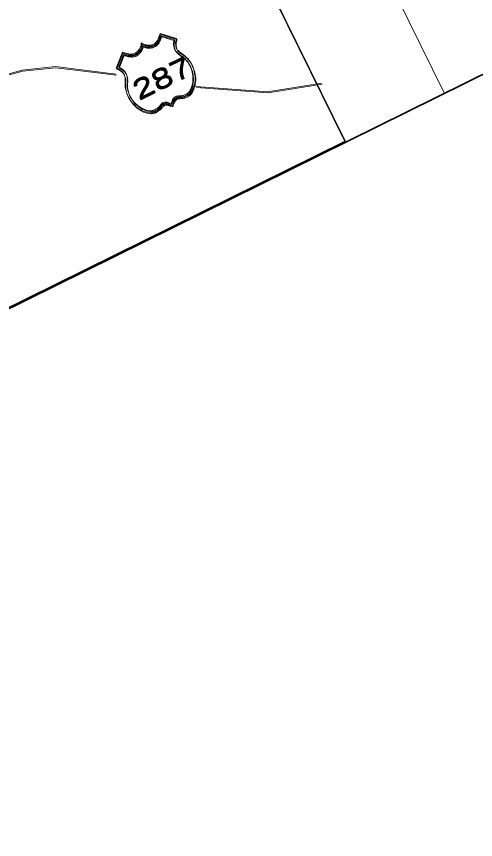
# Model space of a CAD drawing. Extents: x 2356606 to 2371222, y 6973096 to 6982644.
# Drawn here: x 2357523 to 2357641.7, y 6973406.8 to 6973619.6 of the extents above; entities that cross this region are included whole.
import ezdxf

# ---------------------------------------------------------------- set-up
doc = ezdxf.new("R2010")
doc.units = 0
doc.header["$LTSCALE"] = 2
doc.layers.add('62', color=7, linetype='Continuous', lineweight=13)
doc.layers.add('63', color=7, linetype='Continuous', lineweight=13)

msp = doc.modelspace()

# ---------------------------------------------------------------- linework, layer by layer
at = {"layer": '62'}
for p, q in [((2357278.212, 6974319.925), (2357633.685, 6973599.663)), ((2357533.197, 6973606.326), (2357548.847, 6973604.414)), ((2357602.042, 6973602.084), (2357588.059, 6973599.854)), ((2357588.059, 6973599.854), (2357569.519, 6973601.167))]:
    msp.add_line(p, q, dxfattribs=at)
at = {"layer": '62', "lineweight": 25}
msp.add_lwpolyline([(2356999.05, 6973805.301), (2357204.965, 6973388.075), (2357608.13, 6973587.05), (2357402.214, 6974004.278)], dxfattribs=at)
at = {"layer": '62'}
for points in [[(2357533.197, 6973606.326), (2357524.62, 6973605.458), (2357515.167, 6973602.848), (2357498.075, 6973598.379), (2357486.108, 6973599.448), (2357477.959, 6973600.342), (2357467.348, 6973601.705), (2357455.307, 6973606.229), (2357445.287, 6973612.652), (2357434.9, 6973620.272), (2357421.318, 6973628.676), (2357410.865, 6973633.077), (2357401.996, 6973638.183), (2357391.636, 6973644.988), (2357385.904, 6973647.606), (2357373.931, 6973655.899)], [(2357548.927, 6973605.934), (2357550.526, 6973610.06), (2357550.769, 6973609.979), (2357551.018, 6973609.876), (2357551.269, 6973609.825), (2357551.491, 6973609.732), (2357551.744, 6973609.684), (2357551.965, 6973609.64), (2357552.185, 6973609.6), (2357552.426, 6973609.567), (2357552.608, 6973609.556), (2357552.829, 6973609.565), (2357553.03, 6973609.563), (2357553.233, 6973609.613), (2357553.415, 6973609.653), (2357553.573, 6973609.684), (2357553.777, 6973609.781), (2357553.958, 6973609.871), (2357554.06, 6973609.972), (2357554.179, 6973610.082), (2357554.331, 6973610.182), (2357554.462, 6973610.322), (2357554.596, 6973610.463), (2357554.696, 6973610.613), (2357554.829, 6973610.753), (2357554.95, 6973610.912), (2357555.032, 6973611.103), (2357555.133, 6973611.304), (2357555.215, 6973611.495), (2357555.305, 6973611.664), (2357555.337, 6973611.858), (2357555.388, 6973612.057), (2357555.36, 6973612.269), (2357555.39, 6973612.46), (2357555.56, 6973612.37), (2357555.752, 6973612.238), (2357555.951, 6973612.136), (2357556.134, 6973612.073), (2357556.345, 6973612.002), (2357556.565, 6973611.96), (2357556.755, 6973611.93), (2357556.967, 6973611.908), (2357557.176, 6973611.887), (2357557.369, 6973611.857), (2357557.591, 6973611.914), (2357557.774, 6973611.905), (2357558.015, 6973611.973), (2357558.176, 6973612.004), (2357558.397, 6973612.061), (2357558.57, 6973612.122), (2357558.709, 6973612.192), (2357558.88, 6973612.302), (2357558.973, 6973612.422), (2357559.133, 6973612.55), (2357559.265, 6973612.693), (2357559.367, 6973612.844), (2357559.47, 6973612.992), (2357559.6, 6973613.184), (2357559.682, 6973613.375), (2357559.793, 6973613.553), (2357559.864, 6973613.766), (2357559.986, 6973613.976), (2357560.06, 6973614.187), (2357560.139, 6973614.429), (2357560.201, 6973614.66), (2357560.293, 6973614.881), (2357564.545, 6973613.641), (2357564.421, 6973613.228), (2357564.298, 6973612.817), (2357564.284, 6973612.384), (2357564.323, 6973611.952), (2357564.352, 6973611.538), (2357564.438, 6973611.205), (2357564.569, 6973610.944), (2357564.658, 6973610.762), (2357564.78, 6973610.62), (2357564.93, 6973610.47), (2357565.069, 6973610.336), (2357565.249, 6973610.175), (2357565.449, 6973610.024), (2357565.651, 6973609.872), (2357565.882, 6973609.71), (2357566.112, 6973609.548), (2357566.352, 6973609.364), (2357566.583, 6973609.203), (2357566.814, 6973608.989), (2357567.024, 6973608.816), (2357567.214, 6973608.635), (2357567.404, 6973608.454), (2357567.584, 6973608.241), (2357567.733, 6973608.04), (2357568.043, 6973607.564), (2357568.355, 6973607.09), (2357568.582, 6973606.626), (2357568.76, 6973606.112), (2357568.959, 6973605.609), (2357569.099, 6973605.123), (2357569.195, 6973604.62), (2357569.272, 6973604.107), (2357569.341, 6973603.615), (2357569.348, 6973603.09)], [(2357568.618, 6973601.877), (2357568.7, 6973602.167), (2357568.723, 6973602.531), (2357568.744, 6973602.892), (2357568.755, 6973603.274), (2357568.738, 6973603.666), (2357568.71, 6973604.08), (2357568.663, 6973604.482), (2357568.572, 6973604.916), (2357568.476, 6973605.369), (2357568.326, 6973605.772), (2357568.176, 6973606.225), (2357567.97, 6973606.651), (2357567.73, 6973607.083), (2357567.499, 6973607.447), (2357567.281, 6973607.79), (2357567.031, 6973608.043), (2357566.789, 6973608.325), (2357566.529, 6973608.55), (2357566.299, 6973608.762), (2357566.048, 6973608.964), (2357565.787, 6973609.135), (2357565.527, 6973609.309), (2357565.305, 6973609.451), (2357565.096, 6973609.623), (2357564.886, 6973609.795), (2357564.665, 6973609.986), (2357564.506, 6973610.159), (2357564.335, 6973610.352), (2357564.174, 6973610.574), (2357564.015, 6973610.846), (2357563.926, 6973611.179), (2357563.838, 6973611.512), (2357563.77, 6973611.854), (2357563.731, 6973612.235), (2357563.762, 6973612.578), (2357563.835, 6973612.941), (2357563.907, 6973613.302), (2357560.542, 6973614.327), (2357560.472, 6973614.116), (2357560.419, 6973613.912), (2357560.358, 6973613.683), (2357560.276, 6973613.491), (2357560.186, 6973613.272), (2357560.072, 6973613.091), (2357559.963, 6973612.911), (2357559.849, 6973612.729), (2357559.718, 6973612.539), (2357559.606, 6973612.359), (2357559.453, 6973612.208), (2357559.313, 6973612.089), (2357559.181, 6973611.946), (2357559.05, 6973611.859), (2357558.92, 6973611.769), (2357558.788, 6973611.677), (2357558.637, 6973611.629), (2357558.464, 6973611.569), (2357558.285, 6973611.48), (2357558.121, 6973611.45), (2357557.89, 6973611.412), (2357557.729, 6973611.382), (2357557.537, 6973611.363), (2357557.317, 6973611.352), (2357557.135, 6973611.365), (2357556.914, 6973611.356), (2357556.745, 6973611.396), (2357556.542, 6973611.449), (2357556.331, 6973611.47), (2357556.141, 6973611.553), (2357555.95, 6973611.632), (2357555.75, 6973611.735), (2357555.697, 6973611.534), (2357555.657, 6973611.314), (2357555.585, 6973611.152), (2357555.523, 6973610.971), (2357555.423, 6973610.821), (2357555.37, 6973610.67), (2357555.259, 6973610.488), (2357555.178, 6973610.349), (2357555.067, 6973610.217), (2357554.946, 6973610.057), (2357554.844, 6973609.956), (2357554.703, 6973609.839), (2357554.582, 6973609.728), (2357554.47, 6973609.597), (2357554.308, 6973609.518), (2357554.188, 6973609.409), (2357554.055, 6973609.317), (2357553.854, 6973609.219), (2357553.643, 6973609.19), (2357553.43, 6973609.111), (2357553.229, 6973609.112), (2357552.997, 6973609.071), (2357552.758, 6973609.054), (2357552.564, 6973609.085), (2357552.314, 6973609.086), (2357552.073, 6973609.118), (2357551.861, 6973609.139), (2357551.638, 6973609.231), (2357551.4, 6973609.261), (2357551.176, 6973609.352)], [(2357550.817, 6973609.476), (2357549.561, 6973606.222), (2357549.963, 6973606.017), (2357550.323, 6973605.793), (2357550.614, 6973605.562), (2357550.894, 6973605.35), (2357551.103, 6973605.076), (2357551.293, 6973604.844), (2357551.433, 6973604.612), (2357551.555, 6973604.32), (2357551.624, 6973604.026), (2357551.701, 6973603.765), (2357551.741, 6973603.482), (2357551.738, 6973603.179), (2357551.758, 6973602.89), (2357551.756, 6973602.588), (2357551.726, 6973602.296), (2357551.702, 6973601.984), (2357551.698, 6973601.331), (2357551.797, 6973600.675), (2357551.923, 6973600.061), (2357552.161, 6973599.426), (2357552.43, 6973598.831), (2357552.748, 6973598.236), (2357553.148, 6973597.679), (2357553.549, 6973597.174), (2357554.009, 6973596.699), (2357554.53, 6973596.253), (2357555.063, 6973595.888), (2357555.605, 6973595.553), (2357556.175, 6973595.31), (2357556.758, 6973595.096), (2357557.341, 6973594.98), (2357557.904, 6973594.908), (2357558.024, 6973594.918), (2357558.177, 6973594.915), (2357558.327, 6973594.967), (2357558.488, 6973595.047), (2357558.619, 6973595.086), (2357558.782, 6973595.165), (2357558.944, 6973595.245), (2357559.105, 6973595.325), (2357559.277, 6973595.434), (2357559.418, 6973595.505), (2357559.578, 6973595.633), (2357559.73, 6973595.735), (2357559.853, 6973595.843), (2357559.994, 6973595.964), (2357560.106, 6973596.095), (2357560.216, 6973596.175), (2357560.298, 6973596.315), (2357560.407, 6973596.447), (2357560.481, 6973596.554), (2357560.59, 6973596.686), (2357560.712, 6973596.796), (2357560.824, 6973596.876), (2357560.945, 6973596.984), (2357561.086, 6973597.056), (2357561.247, 6973597.085), (2357561.45, 6973597.135), (2357561.63, 6973597.174), (2357561.849, 6973597.131), (2357562.113, 6973597.111), (2357562.414, 6973597.009), (2357562.755, 6973596.926), (2357563.098, 6973596.793), (2357563.229, 6973597.186), (2357563.362, 6973597.527), (2357563.504, 6973597.796), (2357563.658, 6973598.049), (2357563.789, 6973598.239), (2357563.95, 6973598.369), (2357564.092, 6973598.489), (2357564.294, 6973598.589), (2357564.436, 6973598.659), (2357564.596, 6973598.688), (2357564.797, 6973598.737), (2357564.988, 6973598.756), (2357565.171, 6973598.747), (2357565.36, 6973598.766), (2357565.573, 6973598.792), (2357565.795, 6973598.801), (2357566.006, 6973598.831), (2357566.215, 6973598.86), (2357566.408, 6973598.929), (2357566.611, 6973599.03), (2357566.804, 6973599.099), (2357566.995, 6973599.218), (2357567.175, 6973599.309), (2357567.356, 6973599.448), (2357567.54, 6973599.588), (2357567.691, 6973599.738), (2357567.844, 6973599.938), (2357567.985, 6973600.109), (2357568.106, 6973600.32), (2357568.249, 6973600.54), (2357568.331, 6973600.782), (2357568.422, 6973601.053), (2357568.514, 6973601.273), (2357568.566, 6973601.575), (2357568.618, 6973601.877)], [(2357551.176, 6973609.352), (2357550.997, 6973609.413), (2357550.817, 6973609.476)], [(2357549.859, 6973605.515), (2357549.447, 6973605.738), (2357548.927, 6973605.934)], [(2357569.348, 6973603.09), (2357569.315, 6973602.598), (2357569.222, 6973602.125), (2357569.17, 6973601.621), (2357568.984, 6973601.13), (2357568.843, 6973600.657), (2357568.62, 6973600.196), (2357568.487, 6973599.955), (2357568.367, 6973599.746), (2357568.212, 6973599.545), (2357568.051, 6973599.365), (2357567.911, 6973599.193), (2357567.717, 6973599.074), (2357567.516, 6973598.922), (2357567.355, 6973598.795), (2357567.131, 6973598.685), (2357566.928, 6973598.584), (2357566.739, 6973598.517), (2357566.568, 6973598.457), (2357566.337, 6973598.419), (2357566.154, 6973598.377), (2357565.973, 6973598.337), (2357565.771, 6973598.34), (2357565.582, 6973598.321), (2357565.389, 6973598.3), (2357565.239, 6973598.303), (2357565.048, 6973598.282), (2357564.916, 6973598.243), (2357564.734, 6973598.204), (2357564.555, 6973598.166), (2357564.422, 6973598.073), (2357564.28, 6973597.953), (2357564.128, 6973597.805), (2357564.017, 6973597.624), (2357563.885, 6973597.434), (2357563.753, 6973597.192), (2357563.641, 6973596.912), (2357563.538, 6973596.56), (2357563.425, 6973596.179), (2357563.062, 6973596.3), (2357562.764, 6973596.403), (2357562.481, 6973596.515), (2357562.21, 6973596.557), (2357562.01, 6973596.606), (2357561.809, 6973596.608), (2357561.636, 6973596.6), (2357561.477, 6973596.57), (2357561.345, 6973596.531), (2357561.203, 6973596.46), (2357561.083, 6973596.401), (2357560.963, 6973596.293), (2357560.882, 6973596.203), (2357560.749, 6973596.111), (2357560.649, 6973595.961), (2357560.546, 6973595.862), (2357560.456, 6973595.742), (2357560.335, 6973595.63), (2357560.203, 6973595.492), (2357560.04, 6973595.36), (2357559.898, 6973595.241), (2357559.727, 6973595.131), (2357559.567, 6973594.999), (2357559.427, 6973594.881), (2357559.224, 6973594.782), (2357559.041, 6973594.692), (2357558.858, 6973594.6), (2357558.618, 6973594.531), (2357558.415, 6973594.482), (2357558.184, 6973594.444), (2357557.943, 6973594.425), (2357557.691, 6973594.427), (2357557.077, 6973594.5), (2357556.443, 6973594.664), (2357555.82, 6973594.859), (2357555.248, 6973595.154), (2357554.678, 6973595.497), (2357554.156, 6973595.894), (2357553.687, 6973596.339), (2357553.215, 6973596.835), (2357552.785, 6973597.348), (2357552.415, 6973597.895), (2357552.077, 6973598.481), (2357551.786, 6973599.066), (2357551.557, 6973599.682), (2357551.383, 6973600.294), (2357551.264, 6973600.94), (2357551.216, 6973601.543), (2357551.197, 6973601.786), (2357551.188, 6973602.057), (2357551.211, 6973602.319), (2357551.212, 6973602.619), (2357551.216, 6973602.922), (2357551.215, 6973603.222), (2357551.197, 6973603.517), (2357551.128, 6973603.807), (2357551.049, 6973604.119), (2357550.901, 6973604.424), (2357550.731, 6973604.715), (2357550.5, 6973604.979), (2357550.211, 6973605.262), (2357549.859, 6973605.515)]]:
    msp.add_lwpolyline(points, dxfattribs=at)
at = {"layer": '63', "lineweight": 35}
msp.add_line((2357204.965, 6973388.075), (2357788.759, 6973676.197), dxfattribs=at)
at = {"layer": '63'}
for p, q in [((2357533.067, 6973606.589), (2357548.717, 6973604.677)), ((2357587.929, 6973600.117), (2357569.389, 6973601.43)), ((2357601.912, 6973602.347), (2357587.929, 6973600.117))]:
    msp.add_line(p, q, dxfattribs=at)
at = {"layer": '63', "lineweight": 25}
msp.add_lwpolyline([(2356998.92, 6973805.564), (2357204.835, 6973388.338), (2357608, 6973587.313), (2357402.084, 6974004.541)], dxfattribs=at)
at = {"layer": '63'}
for points in [[(2357533.067, 6973606.589), (2357524.49, 6973605.721), (2357515.037, 6973603.111), (2357497.945, 6973598.642), (2357485.978, 6973599.711), (2357477.829, 6973600.605), (2357467.218, 6973601.968), (2357455.177, 6973606.492), (2357445.157, 6973612.915), (2357434.77, 6973620.535), (2357421.188, 6973628.939), (2357410.735, 6973633.34), (2357401.866, 6973638.446), (2357391.506, 6973645.251), (2357385.774, 6973647.869), (2357373.801, 6973656.162)], [(2357548.797, 6973606.197), (2357550.396, 6973610.323), (2357550.639, 6973610.242), (2357550.888, 6973610.139), (2357551.139, 6973610.088), (2357551.361, 6973609.995), (2357551.614, 6973609.947), (2357551.835, 6973609.903), (2357552.055, 6973609.863), (2357552.296, 6973609.83), (2357552.478, 6973609.819), (2357552.699, 6973609.828), (2357552.9, 6973609.826), (2357553.103, 6973609.876), (2357553.285, 6973609.916), (2357553.443, 6973609.947), (2357553.647, 6973610.044), (2357553.828, 6973610.134), (2357553.93, 6973610.235), (2357554.049, 6973610.345), (2357554.201, 6973610.445), (2357554.332, 6973610.585), (2357554.466, 6973610.726), (2357554.566, 6973610.876), (2357554.699, 6973611.016), (2357554.82, 6973611.175), (2357554.902, 6973611.366), (2357555.003, 6973611.567), (2357555.085, 6973611.758), (2357555.175, 6973611.927), (2357555.207, 6973612.121), (2357555.258, 6973612.32), (2357555.23, 6973612.532), (2357555.26, 6973612.723), (2357555.43, 6973612.633), (2357555.622, 6973612.501), (2357555.821, 6973612.399), (2357556.004, 6973612.336), (2357556.215, 6973612.265), (2357556.435, 6973612.223), (2357556.625, 6973612.193), (2357556.837, 6973612.171), (2357557.046, 6973612.15), (2357557.239, 6973612.12), (2357557.461, 6973612.177), (2357557.644, 6973612.168), (2357557.885, 6973612.236), (2357558.046, 6973612.267), (2357558.267, 6973612.324), (2357558.44, 6973612.385), (2357558.579, 6973612.455), (2357558.75, 6973612.565), (2357558.843, 6973612.685), (2357559.003, 6973612.813), (2357559.135, 6973612.956), (2357559.237, 6973613.107), (2357559.34, 6973613.255), (2357559.47, 6973613.447), (2357559.552, 6973613.638), (2357559.663, 6973613.816), (2357559.734, 6973614.029), (2357559.856, 6973614.239), (2357559.93, 6973614.45), (2357560.009, 6973614.692), (2357560.071, 6973614.923), (2357560.163, 6973615.144), (2357564.415, 6973613.904), (2357564.291, 6973613.491), (2357564.168, 6973613.08), (2357564.154, 6973612.647), (2357564.193, 6973612.215), (2357564.222, 6973611.801), (2357564.308, 6973611.468), (2357564.439, 6973611.207), (2357564.528, 6973611.025), (2357564.65, 6973610.883), (2357564.8, 6973610.733), (2357564.939, 6973610.599), (2357565.119, 6973610.438), (2357565.319, 6973610.287), (2357565.521, 6973610.135), (2357565.752, 6973609.973), (2357565.982, 6973609.811), (2357566.222, 6973609.627), (2357566.453, 6973609.466), (2357566.684, 6973609.252), (2357566.894, 6973609.079), (2357567.084, 6973608.898), (2357567.274, 6973608.717), (2357567.454, 6973608.504), (2357567.603, 6973608.303), (2357567.913, 6973607.827), (2357568.225, 6973607.353), (2357568.452, 6973606.889), (2357568.63, 6973606.375), (2357568.829, 6973605.872), (2357568.969, 6973605.386), (2357569.065, 6973604.883), (2357569.142, 6973604.37), (2357569.211, 6973603.878), (2357569.218, 6973603.353)], [(2357568.488, 6973602.14), (2357568.57, 6973602.43), (2357568.593, 6973602.794), (2357568.614, 6973603.155), (2357568.625, 6973603.537), (2357568.608, 6973603.929), (2357568.58, 6973604.343), (2357568.533, 6973604.745), (2357568.442, 6973605.179), (2357568.346, 6973605.632), (2357568.196, 6973606.035), (2357568.046, 6973606.488), (2357567.84, 6973606.914), (2357567.6, 6973607.346), (2357567.369, 6973607.71), (2357567.151, 6973608.053), (2357566.901, 6973608.306), (2357566.659, 6973608.588), (2357566.399, 6973608.813), (2357566.169, 6973609.025), (2357565.918, 6973609.227), (2357565.657, 6973609.398), (2357565.397, 6973609.572), (2357565.175, 6973609.714), (2357564.966, 6973609.886), (2357564.756, 6973610.058), (2357564.535, 6973610.249), (2357564.376, 6973610.422), (2357564.205, 6973610.615), (2357564.044, 6973610.837), (2357563.885, 6973611.109), (2357563.796, 6973611.442), (2357563.708, 6973611.775), (2357563.64, 6973612.117), (2357563.601, 6973612.498), (2357563.632, 6973612.841), (2357563.705, 6973613.204), (2357563.777, 6973613.565), (2357560.412, 6973614.59), (2357560.342, 6973614.379), (2357560.289, 6973614.175), (2357560.228, 6973613.946), (2357560.146, 6973613.754), (2357560.056, 6973613.535), (2357559.942, 6973613.354), (2357559.833, 6973613.174), (2357559.719, 6973612.992), (2357559.588, 6973612.802), (2357559.476, 6973612.622), (2357559.323, 6973612.471), (2357559.183, 6973612.352), (2357559.051, 6973612.209), (2357558.92, 6973612.122), (2357558.79, 6973612.032), (2357558.658, 6973611.94), (2357558.507, 6973611.892), (2357558.334, 6973611.832), (2357558.155, 6973611.743), (2357557.991, 6973611.713), (2357557.76, 6973611.675), (2357557.599, 6973611.645), (2357557.407, 6973611.626), (2357557.187, 6973611.615), (2357557.005, 6973611.628), (2357556.784, 6973611.619), (2357556.615, 6973611.659), (2357556.412, 6973611.712), (2357556.201, 6973611.733), (2357556.011, 6973611.816), (2357555.82, 6973611.895), (2357555.62, 6973611.998), (2357555.567, 6973611.797), (2357555.527, 6973611.577), (2357555.455, 6973611.415), (2357555.393, 6973611.234), (2357555.293, 6973611.084), (2357555.24, 6973610.933), (2357555.129, 6973610.751), (2357555.048, 6973610.612), (2357554.937, 6973610.48), (2357554.816, 6973610.32), (2357554.714, 6973610.219), (2357554.573, 6973610.102), (2357554.452, 6973609.991), (2357554.34, 6973609.86), (2357554.178, 6973609.781), (2357554.058, 6973609.672), (2357553.925, 6973609.58), (2357553.724, 6973609.482), (2357553.513, 6973609.453), (2357553.3, 6973609.374), (2357553.099, 6973609.375), (2357552.867, 6973609.334), (2357552.628, 6973609.317), (2357552.434, 6973609.348), (2357552.184, 6973609.349), (2357551.943, 6973609.381), (2357551.731, 6973609.402), (2357551.508, 6973609.494), (2357551.27, 6973609.524), (2357551.046, 6973609.615)], [(2357550.687, 6973609.739), (2357549.431, 6973606.485), (2357549.833, 6973606.28), (2357550.193, 6973606.056), (2357550.484, 6973605.825), (2357550.764, 6973605.613), (2357550.973, 6973605.339), (2357551.163, 6973605.107), (2357551.303, 6973604.875), (2357551.425, 6973604.583), (2357551.494, 6973604.289), (2357551.571, 6973604.028), (2357551.611, 6973603.745), (2357551.608, 6973603.442), (2357551.628, 6973603.153), (2357551.626, 6973602.851), (2357551.596, 6973602.559), (2357551.572, 6973602.247), (2357551.568, 6973601.594), (2357551.667, 6973600.938), (2357551.793, 6973600.324), (2357552.031, 6973599.689), (2357552.3, 6973599.094), (2357552.618, 6973598.499), (2357553.018, 6973597.942), (2357553.419, 6973597.437), (2357553.879, 6973596.962), (2357554.4, 6973596.516), (2357554.933, 6973596.151), (2357555.475, 6973595.816), (2357556.045, 6973595.573), (2357556.628, 6973595.359), (2357557.211, 6973595.243), (2357557.774, 6973595.171), (2357557.894, 6973595.181), (2357558.047, 6973595.178), (2357558.197, 6973595.23), (2357558.358, 6973595.31), (2357558.489, 6973595.349), (2357558.652, 6973595.428), (2357558.814, 6973595.508), (2357558.975, 6973595.588), (2357559.147, 6973595.697), (2357559.288, 6973595.768), (2357559.448, 6973595.896), (2357559.6, 6973595.998), (2357559.723, 6973596.106), (2357559.864, 6973596.227), (2357559.976, 6973596.358), (2357560.086, 6973596.438), (2357560.168, 6973596.578), (2357560.277, 6973596.71), (2357560.351, 6973596.817), (2357560.46, 6973596.949), (2357560.582, 6973597.059), (2357560.694, 6973597.139), (2357560.815, 6973597.247), (2357560.956, 6973597.319), (2357561.117, 6973597.348), (2357561.32, 6973597.398), (2357561.5, 6973597.437), (2357561.719, 6973597.394), (2357561.983, 6973597.374), (2357562.284, 6973597.272), (2357562.625, 6973597.189), (2357562.968, 6973597.056), (2357563.099, 6973597.449), (2357563.232, 6973597.79), (2357563.374, 6973598.059), (2357563.528, 6973598.312), (2357563.659, 6973598.502), (2357563.82, 6973598.632), (2357563.962, 6973598.752), (2357564.164, 6973598.852), (2357564.306, 6973598.922), (2357564.466, 6973598.951), (2357564.667, 6973599), (2357564.858, 6973599.019), (2357565.041, 6973599.01), (2357565.23, 6973599.029), (2357565.443, 6973599.055), (2357565.665, 6973599.064), (2357565.876, 6973599.094), (2357566.085, 6973599.123), (2357566.278, 6973599.192), (2357566.481, 6973599.293), (2357566.674, 6973599.362), (2357566.865, 6973599.481), (2357567.045, 6973599.572), (2357567.226, 6973599.711), (2357567.41, 6973599.851), (2357567.561, 6973600.001), (2357567.714, 6973600.201), (2357567.855, 6973600.372), (2357567.976, 6973600.583), (2357568.119, 6973600.803), (2357568.201, 6973601.045), (2357568.292, 6973601.316), (2357568.384, 6973601.536), (2357568.436, 6973601.838), (2357568.488, 6973602.14)], [(2357551.046, 6973609.615), (2357550.867, 6973609.676), (2357550.687, 6973609.739)], [(2357549.729, 6973605.778), (2357549.317, 6973606.001), (2357548.797, 6973606.197)], [(2357569.218, 6973603.353), (2357569.185, 6973602.861), (2357569.092, 6973602.388), (2357569.04, 6973601.884), (2357568.854, 6973601.393), (2357568.713, 6973600.92), (2357568.49, 6973600.459), (2357568.357, 6973600.218), (2357568.237, 6973600.009), (2357568.082, 6973599.808), (2357567.921, 6973599.628), (2357567.781, 6973599.456), (2357567.587, 6973599.337), (2357567.386, 6973599.185), (2357567.225, 6973599.058), (2357567.001, 6973598.948), (2357566.798, 6973598.847), (2357566.609, 6973598.78), (2357566.438, 6973598.72), (2357566.207, 6973598.682), (2357566.024, 6973598.64), (2357565.843, 6973598.6), (2357565.641, 6973598.603), (2357565.452, 6973598.584), (2357565.259, 6973598.563), (2357565.109, 6973598.566), (2357564.918, 6973598.545), (2357564.786, 6973598.506), (2357564.604, 6973598.467), (2357564.425, 6973598.429), (2357564.292, 6973598.336), (2357564.15, 6973598.216), (2357563.998, 6973598.068), (2357563.887, 6973597.887), (2357563.755, 6973597.697), (2357563.623, 6973597.455), (2357563.511, 6973597.175), (2357563.408, 6973596.823), (2357563.295, 6973596.442), (2357562.932, 6973596.563), (2357562.634, 6973596.666), (2357562.351, 6973596.778), (2357562.08, 6973596.82), (2357561.88, 6973596.869), (2357561.679, 6973596.871), (2357561.506, 6973596.863), (2357561.347, 6973596.833), (2357561.215, 6973596.794), (2357561.073, 6973596.723), (2357560.953, 6973596.664), (2357560.833, 6973596.556), (2357560.752, 6973596.466), (2357560.619, 6973596.374), (2357560.519, 6973596.224), (2357560.416, 6973596.125), (2357560.326, 6973596.005), (2357560.205, 6973595.893), (2357560.073, 6973595.755), (2357559.91, 6973595.623), (2357559.768, 6973595.504), (2357559.597, 6973595.394), (2357559.437, 6973595.262), (2357559.297, 6973595.144), (2357559.094, 6973595.045), (2357558.911, 6973594.955), (2357558.728, 6973594.863), (2357558.488, 6973594.794), (2357558.285, 6973594.745), (2357558.054, 6973594.707), (2357557.813, 6973594.688), (2357557.561, 6973594.69), (2357556.947, 6973594.763), (2357556.313, 6973594.927), (2357555.69, 6973595.122), (2357555.118, 6973595.417), (2357554.548, 6973595.76), (2357554.026, 6973596.157), (2357553.557, 6973596.602), (2357553.085, 6973597.098), (2357552.655, 6973597.611), (2357552.285, 6973598.158), (2357551.947, 6973598.744), (2357551.656, 6973599.329), (2357551.427, 6973599.945), (2357551.253, 6973600.557), (2357551.134, 6973601.203), (2357551.086, 6973601.806), (2357551.067, 6973602.049), (2357551.058, 6973602.32), (2357551.081, 6973602.582), (2357551.082, 6973602.882), (2357551.086, 6973603.185), (2357551.085, 6973603.485), (2357551.067, 6973603.78), (2357550.998, 6973604.07), (2357550.919, 6973604.382), (2357550.771, 6973604.687), (2357550.601, 6973604.978), (2357550.37, 6973605.242), (2357550.081, 6973605.525), (2357549.729, 6973605.778)]]:
    msp.add_lwpolyline(points, dxfattribs=at)

# ---------------------------------------------------------------- texts
at = {"layer": '62', "width": 1.4}
msp.add_text('287', height=5.099, rotation=26.268, dxfattribs=at).set_placement((2357554.699, 6973597.643))
at = {"layer": '63', "width": 1.4}
msp.add_text('287', height=5.099, rotation=26.268, dxfattribs=at).set_placement((2357554.569, 6973597.907))

doc.saveas('drawing.dxf')
